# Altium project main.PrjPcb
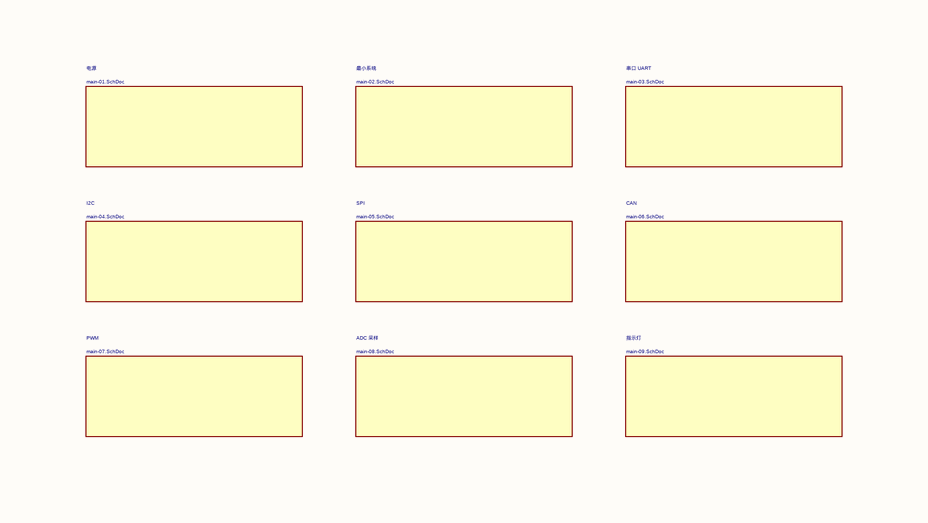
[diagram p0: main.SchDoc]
10 sheets, 84 parts. Net scope: global (net labels, ports and power ports of the same name join across sheets).
Board file: main.PcbDoc
Sheets:
  main.SchDoc
    电源 = main-01.SchDoc
    最小系统 = main-02.SchDoc
    串口 UART = main-03.SchDoc
    I2C = main-04.SchDoc
    SPI = main-05.SchDoc
    CAN = main-06.SchDoc
    PWM = main-07.SchDoc
    ADC 采样 = main-08.SchDoc
    指示灯 = main-09.SchDoc

## Sheet main.SchDoc
size 172 x 96 mm

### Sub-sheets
ADC 采样 = main-08.SchDoc: no entries
CAN = main-06.SchDoc: no entries
I2C = main-04.SchDoc: no entries
PWM = main-07.SchDoc: no entries
SPI = main-05.SchDoc: no entries
串口 UART = main-03.SchDoc: no entries
指示灯 = main-09.SchDoc: no entries
最小系统 = main-02.SchDoc: no entries
电源 = main-01.SchDoc: no entries

## Sheet main-01.SchDoc
size 171 x 140 mm
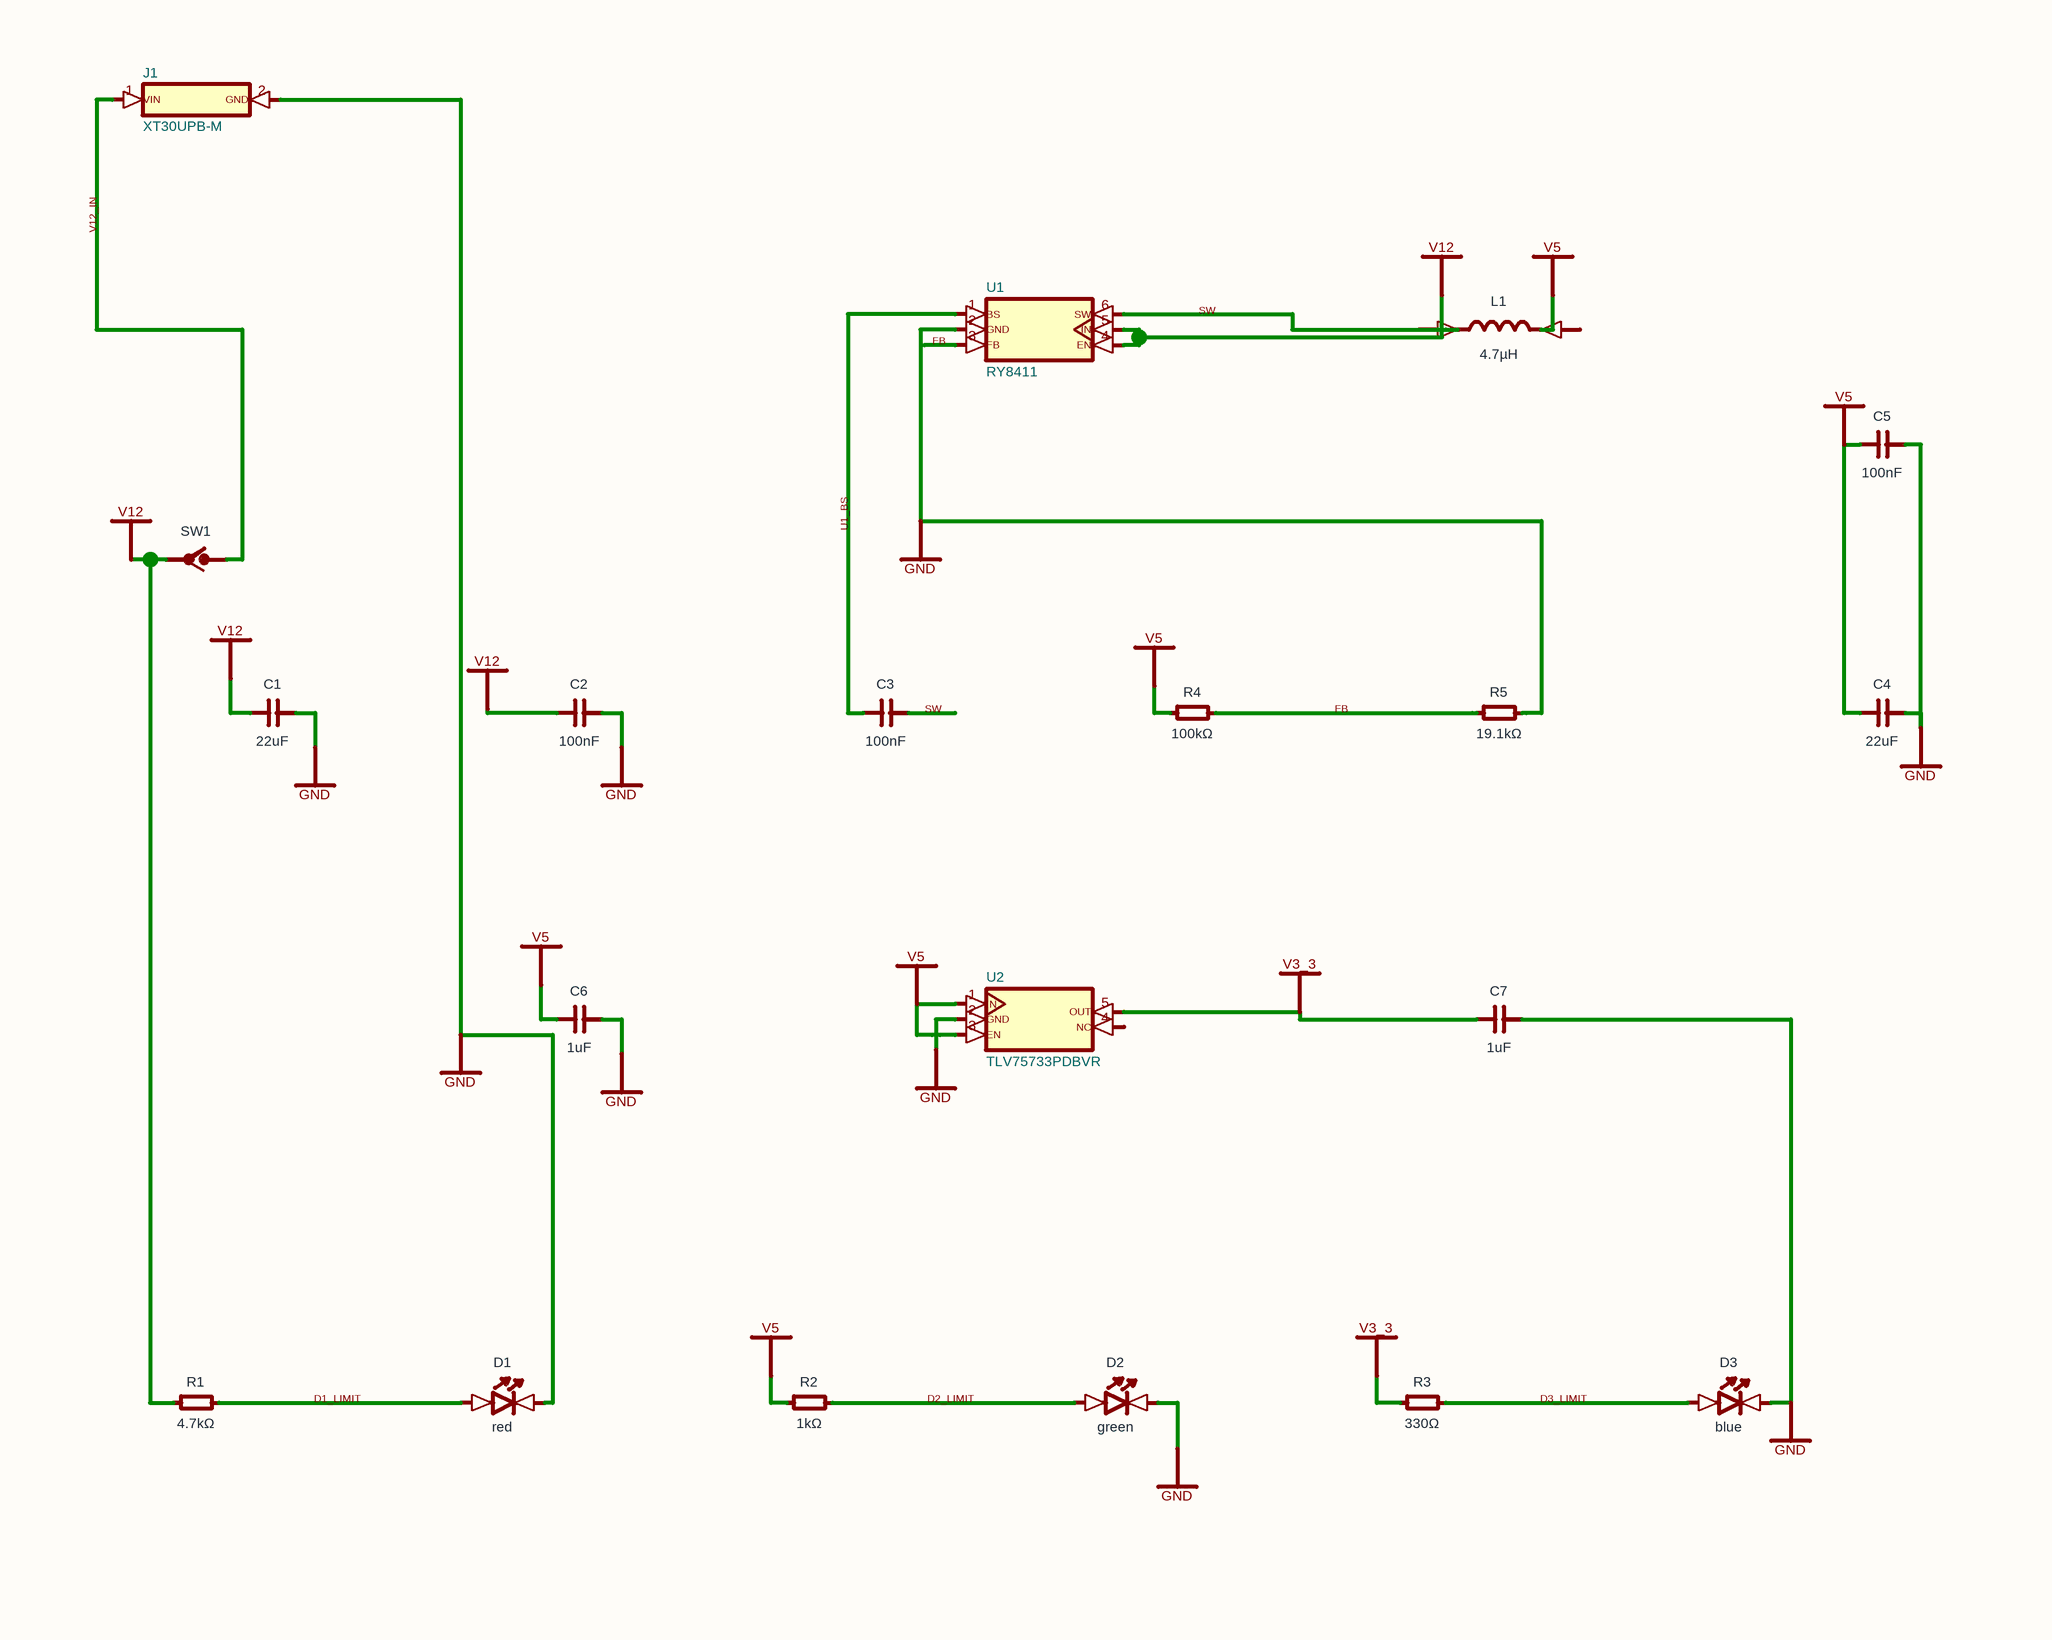
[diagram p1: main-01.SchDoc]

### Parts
C1  22uF
C2  100nF
C3  100nF
C4  22uF
C5  100nF
C6  1uF
C7  1uF
D1  red
D2  green
D3  blue
J1  (no value)
L1  4.7µH
R1  4.7kΩ
R2  1kΩ
R3  330Ω
R4  100kΩ
R5  19.1kΩ
SW1  (no value)
U1  (no value)
U2  (no value)

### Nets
GND: C1.2(neg) C2.2(neg) C4.2(neg) C5.2(neg) C6.2(neg) C7.1(pos) C7.2(neg) D1.2(cathode) D2.1(cathode) D3.1(cathode) J1.2(GND) R3.1(anode) R5.2(cathode) U1.2(GND) U2.2(GND) U2.5(OUT)  [also labelled V3_3]
V5: C4.1(pos) C5.1(pos) C6.1(pos) R2.1(anode) R4.1(anode) U2.1(IN) U2.3(EN)
V12: C1.1(pos) C2.1(pos) R1.1(anode) SW1.1(T1) U1.4(EN) U1.5(IN)
NetC3_1: C3.1(pos) U1.1(BS)
NetD1_1: D1.1(anode) R1.2(cathode)
NetD2_2: D2.2(anode) R2.2(cathode)
NetD3_2: D3.2(anode) R3.2(cathode)
NetJ1_1: J1.1(VIN) SW1.2(COM)
NetL1_1: L1.1(anode) U1.6(SW)
NetR4_2: R4.2(cathode) R5.1(anode)

Not connected (* = marked no-connect by the designer): C3 2(neg); L1 2(cathode); U1 3(FB); U2 4(NC)

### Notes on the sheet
- (near J1) V12_IN
- (near U1) FB
- (near U1) SW
- U1_BS
- (near C3) SW
- FB
- D1_LIMIT
- D2_LIMIT
- D3_LIMIT

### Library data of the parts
C1-C7 = capacitor_right
D1-D3 = led_right
J1 = J1
L1 = inductor_right
R1-R5 = boxresistor_right
SW1 = spst_switch_right
U1 = U1
U2 = U2

## Sheet main-02.SchDoc
size 167 x 125 mm
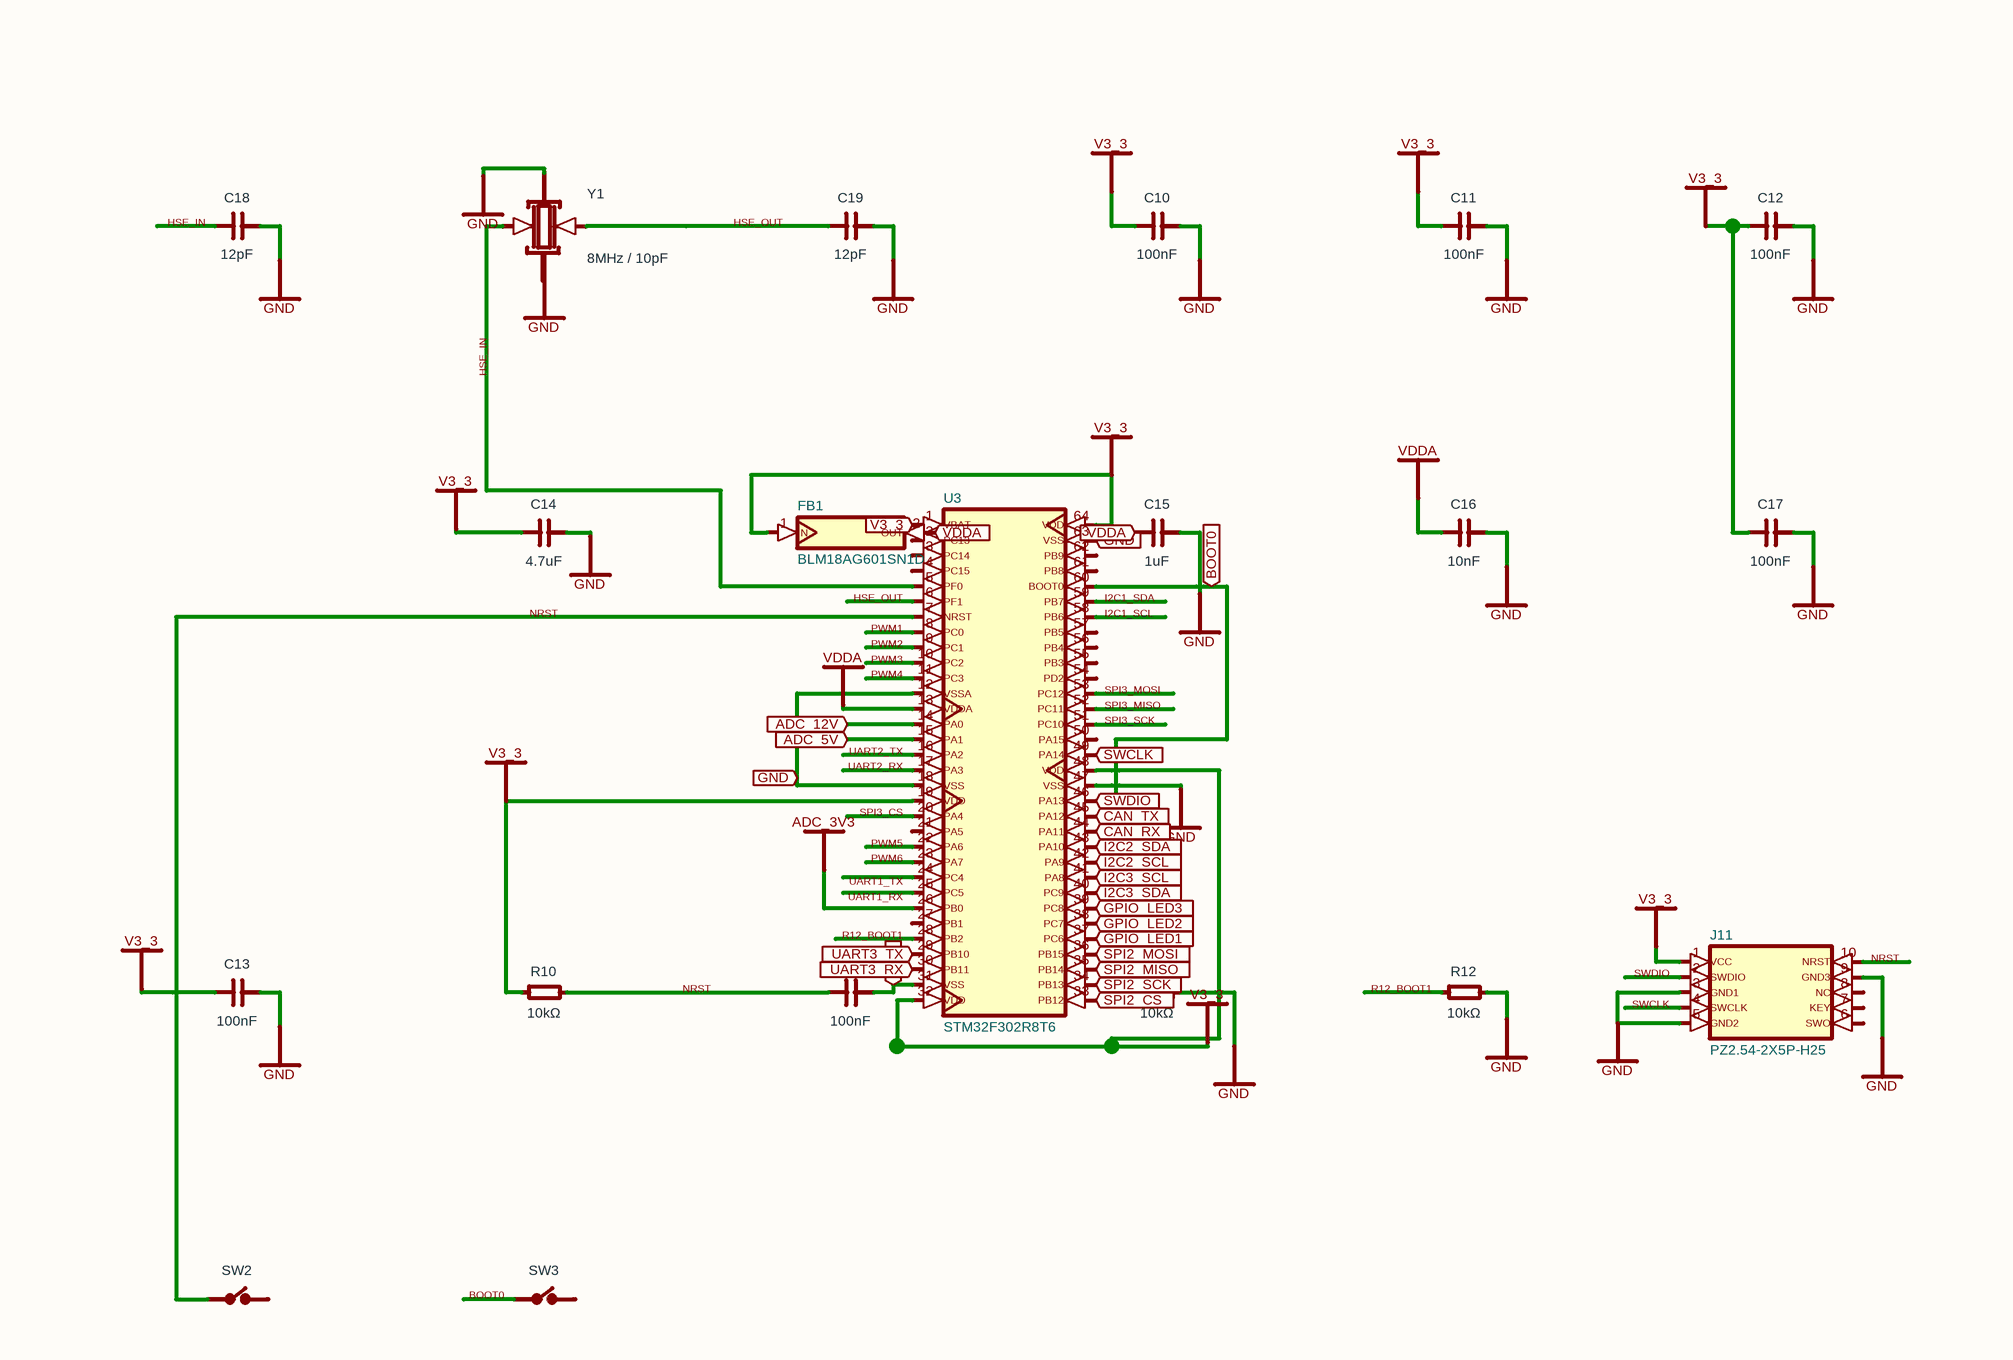
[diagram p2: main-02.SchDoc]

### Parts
C10  100nF
C11  100nF
C12  100nF
C13  100nF
C14  4.7uF
C15  1uF
C16  10nF
C17  100nF
C18  12pF
C19  12pF
C20  100nF
FB1  (no value)
J11  (no value)
R10  10kΩ
R11  10kΩ
R12  10kΩ
SW2  (no value)
SW3  (no value)
U3  (no value)
Y1  8MHz / 10pF

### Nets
ADC_3V3: U3.26(PB0)
ADC_5V: U3.15(PA1)
ADC_12V: U3.14(PA0)
GND: C10.1(pos) C10.2(neg) C11.1(pos) C11.2(neg) C12.1(pos) C12.2(neg) C13.1(pos) C13.2(neg) C14.1(pos) C14.2(neg) C15.2(neg) C16.2(neg) C17.1(pos) C17.2(neg) C18.2(neg) C19.2(neg) C20.2(neg) FB1.1(IN) J11.1(VCC) J11.3(GND1) J11.5(GND2) J11.9(GND3) R10.1(anode) R11.2(cathode) R12.2(cathode) SW2.1(A1) U3.1(VBAT) U3.7(NRST) U3.12(VSSA) U3.18(VSS) U3.19(VDD) U3.31(VSS) U3.32(VDD) U3.47(VSS) U3.48(VDD) U3.63(VSS) U3.64(VDD) Y1.2(gnd2) Y1.4(gnd1)  [also labelled V3_3]
VDDA: C15.1(pos) C16.1(pos) FB1.2(OUT) U3.13(VDDA)
BOOT0: R11.1(anode) U3.60(BOOT0)
CAN_RX: U3.44(PA11)
CAN_TX: U3.45(PA12)
GPIO_LED1: U3.37(PC6)
GPIO_LED2: U3.38(PC7)
GPIO_LED3: U3.39(PC8)
I2C2_SCL: U3.42(PA9)
I2C2_SDA: U3.43(PA10)
I2C3_SCL: U3.41(PA8)
I2C3_SDA: U3.40(PC9)
SPI2_CS: U3.33(PB12)
SPI2_MISO: U3.35(PB14)
SPI2_MOSI: U3.36(PB15)
SPI2_SCK: U3.34(PB13)
SWCLK: U3.49(PA14)
SWDIO: U3.46(PA13)
UART3_RX: U3.30(PB11)
UART3_TX: U3.29(PB10)
NetC19_1: C19.1(pos) Y1.3(X2)
NetC20_1: C20.1(pos) R10.2(cathode)
NetU3_5: U3.5(PF0) Y1.1(X1)

Not connected (* = marked no-connect by the designer): C18 1(pos); J11 2(SWDIO) 4(SWCLK) 6(SWO) 7(KEY) 8(NC) 10(NRST); R12 1(anode); SW2 2(A2); SW3 1(A1) 2(A2); U3 2(PC13) 3(PC14) 4(PC15) 6(PF1) 8(PC0) 9(PC1) 10(PC2) 11(PC3) 16(PA2) 17(PA3) 20(PA4) 21(PA5) 22(PA6) 23(PA7) 24(PC4) 25(PC5) 27(PB1) 28(PB2) 50(PA15) 51(PC10) 52(PC11) 53(PC12) 54(PD2) 55(PB3) 56(PB4) 57(PB5) 58(PB6) 59(PB7) 61(PB8) 62(PB9)

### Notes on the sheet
- (near C18) HSE_IN
- (near C19) HSE_OUT
- (near Y1) HSE_IN
- (near C14) NRST
- HSE_OUT
- (near U3) PWM1
- (near U3) I2C1_SCL
- I2C1_SDA
- (near U3) PWM2
- (near U3) PWM3
- (near U3) PWM4
- (near U3) UART2_TX
- (near U3) UART2_RX
- (near U3) SPI3_CS
- (near U3) SPI3_SCK
- (near U3) SPI3_MISO
- (near U3) SPI3_MOSI
- NRST
- R12_BOOT1
- (near U3) PWM5
- (near U3) PWM6
- (near U3) UART1_TX
- (near U3) UART1_RX
- (near R12) R12_BOOT1
- (near J11) SWDIO
- (near J11) SWCLK
- (near J11) NRST
- (near SW3) BOOT0

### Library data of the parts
C10-C20 = capacitor_right
FB1 = FB1
J11 = J11
R10-R12 = boxresistor_right
SW2 SW3 = spst_switch_right
U3 = U3
Y1 = crystal_4pin_right

## Sheet main-03.SchDoc
size 101 x 114 mm
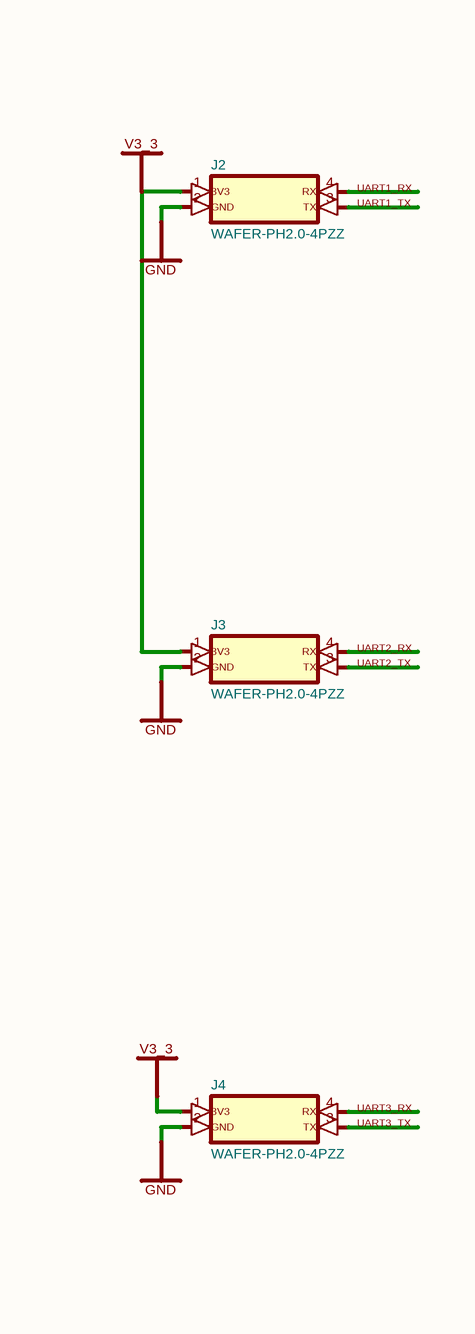
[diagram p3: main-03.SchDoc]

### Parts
J2  (no value)
J3  (no value)
J4  (no value)

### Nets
GND: J2.1(3V3) J2.2(GND) J3.1(3V3) J3.2(GND) J4.1(3V3) J4.2(GND)  [also labelled V3_3]

Not connected (* = marked no-connect by the designer): J2 3(TX) 4(RX); J3 3(TX) 4(RX); J4 3(TX) 4(RX)

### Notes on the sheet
- (near J2) UART1_TX
- (near J2) UART1_RX
- (near J3) UART2_TX
- (near J3) UART2_RX
- (near J4) UART3_TX
- (near J4) UART3_RX

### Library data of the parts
J2 = J2
J3 = J3
J4 = J4

## Sheet main-04.SchDoc
size 158 x 97 mm
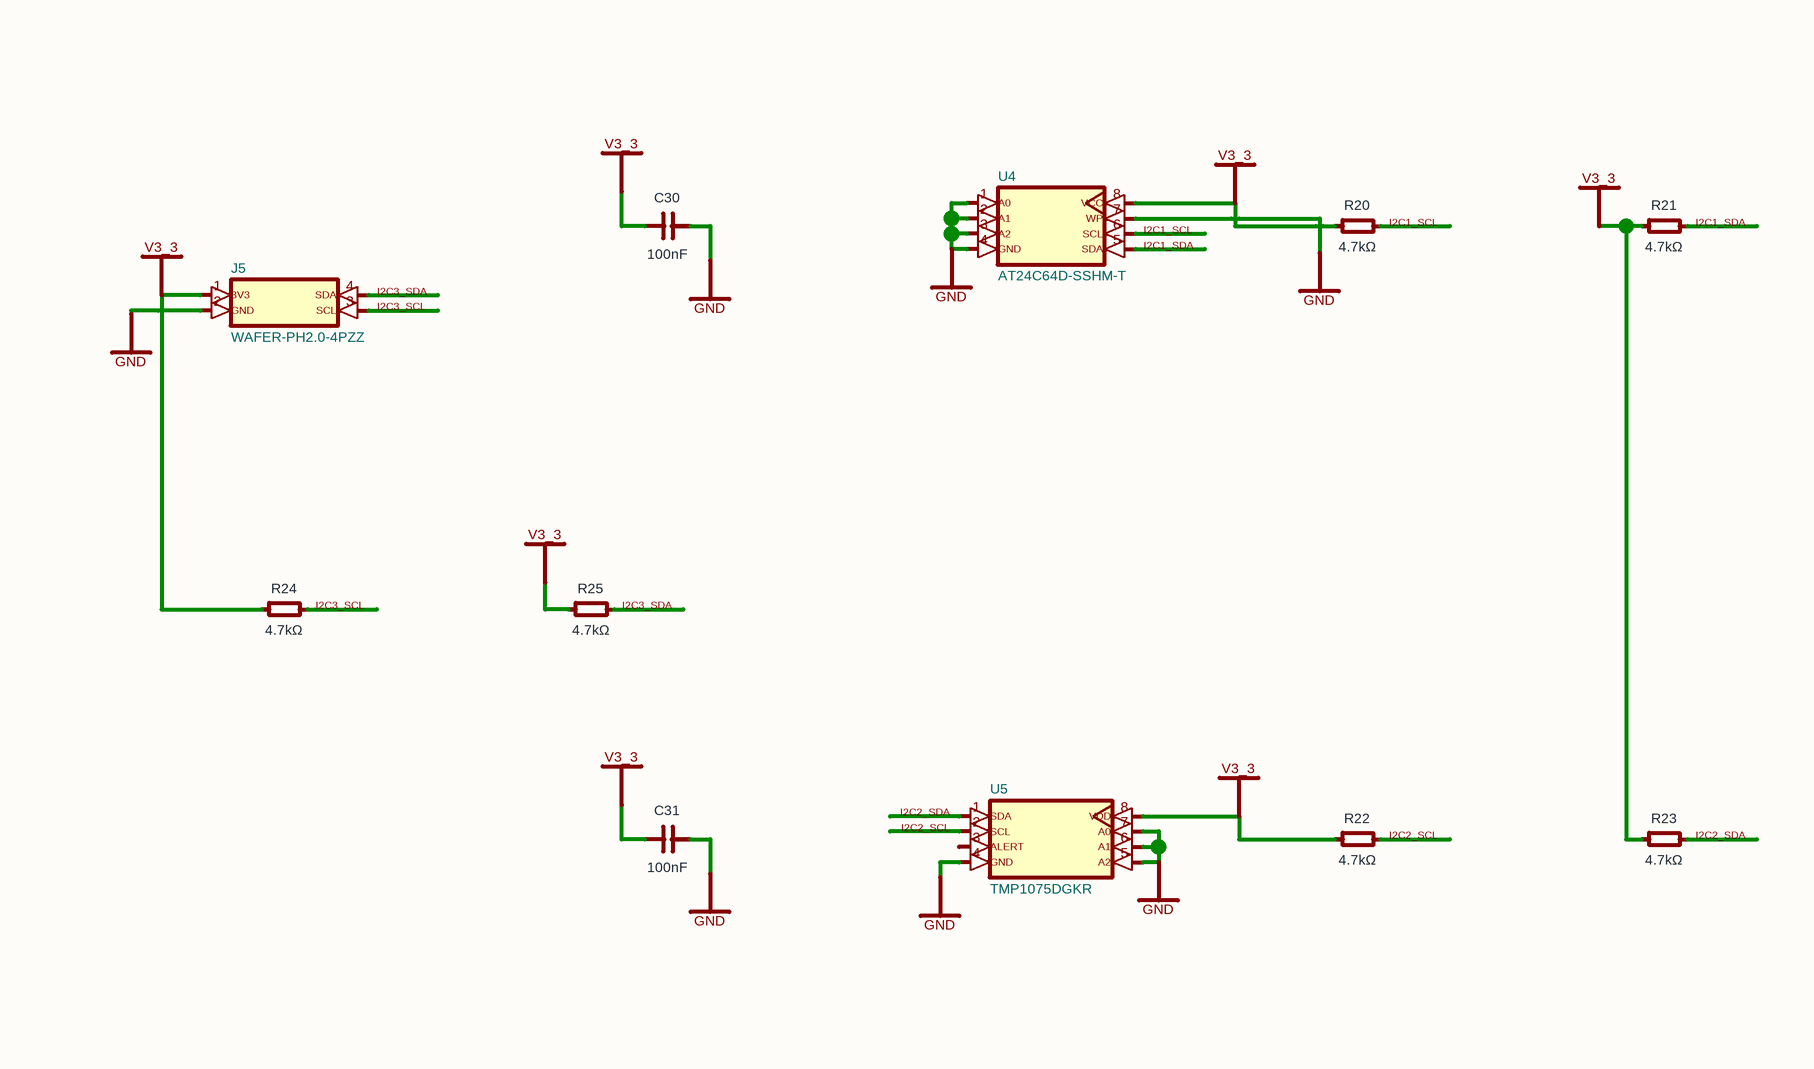
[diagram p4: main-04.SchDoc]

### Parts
C30  100nF
C31  100nF
J5  (no value)
R20  4.7kΩ
R21  4.7kΩ
R22  4.7kΩ
R23  4.7kΩ
R24  4.7kΩ
R25  4.7kΩ
U4  (no value)
U5  (no value)

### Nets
GND: C30.1(pos) C30.2(neg) C31.1(pos) C31.2(neg) J5.1(3V3) J5.2(GND) R20.1(anode) R21.1(anode) R22.1(anode) R23.1(anode) R24.1(anode) R25.1(anode) U4.1(A0) U4.2(A1) U4.3(A2) U4.4(GND) U4.7(WP) U4.8(VCC) U5.4(GND) U5.5(A2) U5.6(A1) U5.7(A0) U5.8(VDD)  [also labelled V3_3]

Not connected (* = marked no-connect by the designer): J5 3(SCL) 4(SDA); R20 2(cathode); R21 2(cathode); R22 2(cathode); R23 2(cathode); R24 2(cathode); R25 2(cathode); U4 5(SDA) 6(SCL); U5 1(SDA) 2(SCL) 3(ALERT)

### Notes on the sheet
- (near J5) I2C3_SCL
- (near J5) I2C3_SDA
- (near U4) I2C1_SDA
- (near U4) I2C1_SCL
- (near R20) I2C1_SCL
- (near R21) I2C1_SDA
- (near R24) I2C3_SCL
- (near R25) I2C3_SDA
- (near U5) I2C2_SDA
- (near U5) I2C2_SCL
- (near R22) I2C2_SCL
- (near R23) I2C2_SDA

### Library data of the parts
C30 C31 = capacitor_right
J5 = J5
R20-R25 = boxresistor_right
U4 = U4
U5 = U5

## Sheet main-05.SchDoc
size 135 x 133 mm
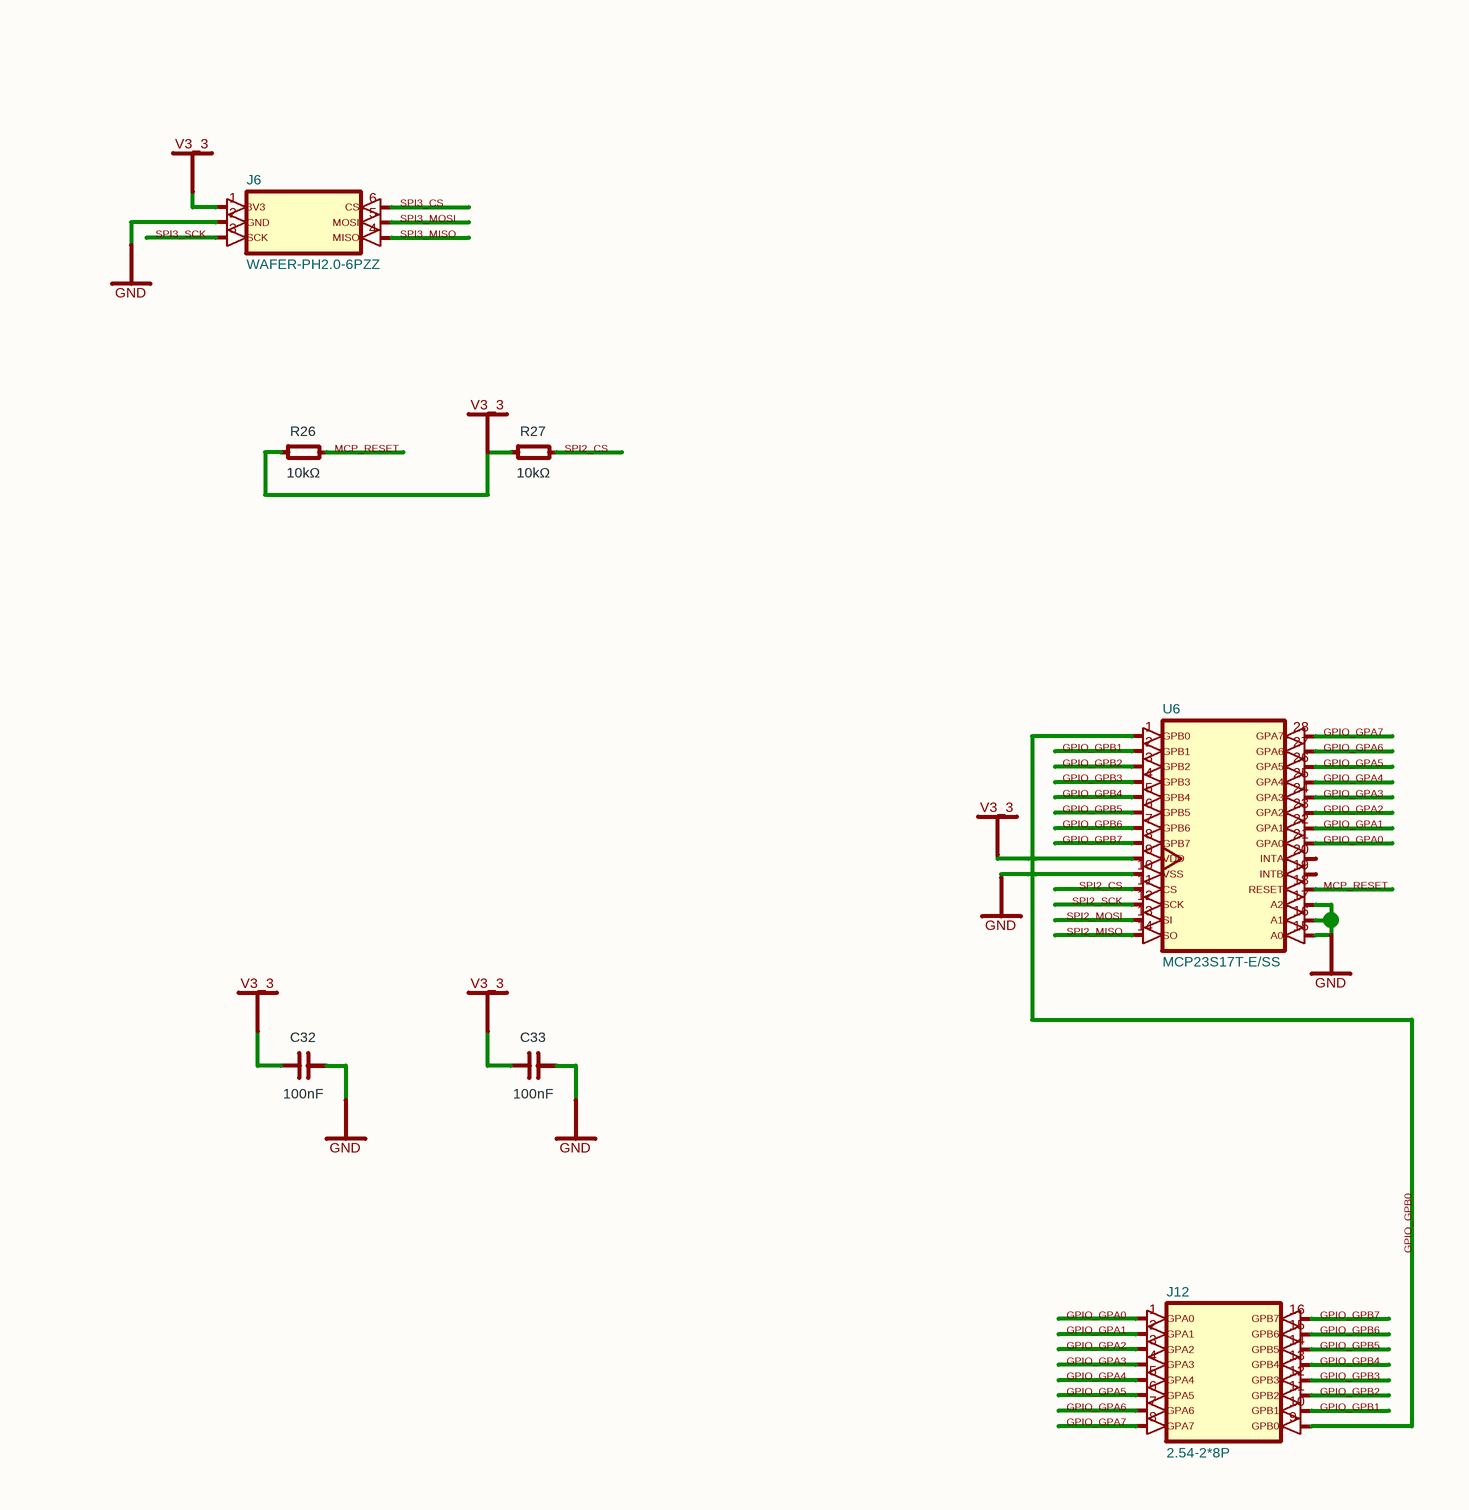
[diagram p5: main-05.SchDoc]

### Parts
C32  100nF
C33  100nF
J6  (no value)
J12  (no value)
R26  10kΩ
R27  10kΩ
U6  (no value)

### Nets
GND: C32.1(pos) C32.2(neg) C33.1(pos) C33.2(neg) J6.1(3V3) J6.2(GND) R26.1(anode) R27.1(anode) U6.9(VDD) U6.10(VSS) U6.15(A0) U6.16(A1) U6.17(A2)  [also labelled V3_3]
NetJ12_9: J12.9(GPB0) U6.1(GPB0)

Not connected (* = marked no-connect by the designer): J6 3(SCK) 4(MISO) 5(MOSI) 6(CS); J12 1(GPA0) 2(GPA1) 3(GPA2) 4(GPA3) 5(GPA4) 6(GPA5) 7(GPA6) 8(GPA7) 10(GPB1) 11(GPB2) 12(GPB3) 13(GPB4) 14(GPB5) 15(GPB6) 16(GPB7); R26 2(cathode); R27 2(cathode); U6 2(GPB1) 3(GPB2) 4(GPB3) 5(GPB4) 6(GPB5) 7(GPB6) 8(GPB7) 11(CS) 12(SCK) 13(SI) 14(SO) 18(RESET) 19(INTB) 20(INTA) 21(GPA0) 22(GPA1) 23(GPA2) 24(GPA3) 25(GPA4) 26(GPA5) 27(GPA6) 28(GPA7)

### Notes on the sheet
- (near J6) SPI3_SCK
- (near J6) SPI3_MISO
- (near J6) SPI3_MOSI
- (near J6) SPI3_CS
- (near R26) MCP_RESET
- (near R27) SPI2_CS
- (near U6) GPIO_GPB1
- (near U6) GPIO_GPA6
- (near U6) GPIO_GPA7
- (near U6) GPIO_GPB2
- (near U6) GPIO_GPB3
- (near U6) GPIO_GPB4
- (near U6) GPIO_GPB5
- (near U6) GPIO_GPB6
- (near U6) GPIO_GPB7
- (near U6) SPI2_CS
- (near U6) SPI2_SCK
- (near U6) SPI2_MOSI
- (near U6) SPI2_MISO
- (near U6) GPIO_GPA0
- (near U6) GPIO_GPA1
- (near U6) GPIO_GPA2
- (near U6) GPIO_GPA3
- (near U6) GPIO_GPA4
- (near U6) GPIO_GPA5
- (near U6) MCP_RESET
- (near J12) GPIO_GPA0
- (near J12) GPIO_GPB7
- (near J12) GPIO_GPB0
- (near J12) GPIO_GPA1
- (near J12) GPIO_GPA2
- (near J12) GPIO_GPA3
- (near J12) GPIO_GPA4
- (near J12) GPIO_GPA5
- (near J12) GPIO_GPA6
- (near J12) GPIO_GPA7
- (near J12) GPIO_GPB1
- (near J12) GPIO_GPB2
- (near J12) GPIO_GPB3
- (near J12) GPIO_GPB4
- (near J12) GPIO_GPB5
- (near J12) GPIO_GPB6

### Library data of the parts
C32 C33 = capacitor_right
J6 = J6
J12 = J12
R26 R27 = boxresistor_right
U6 = U6

## Sheet main-06.SchDoc
size 156 x 94 mm
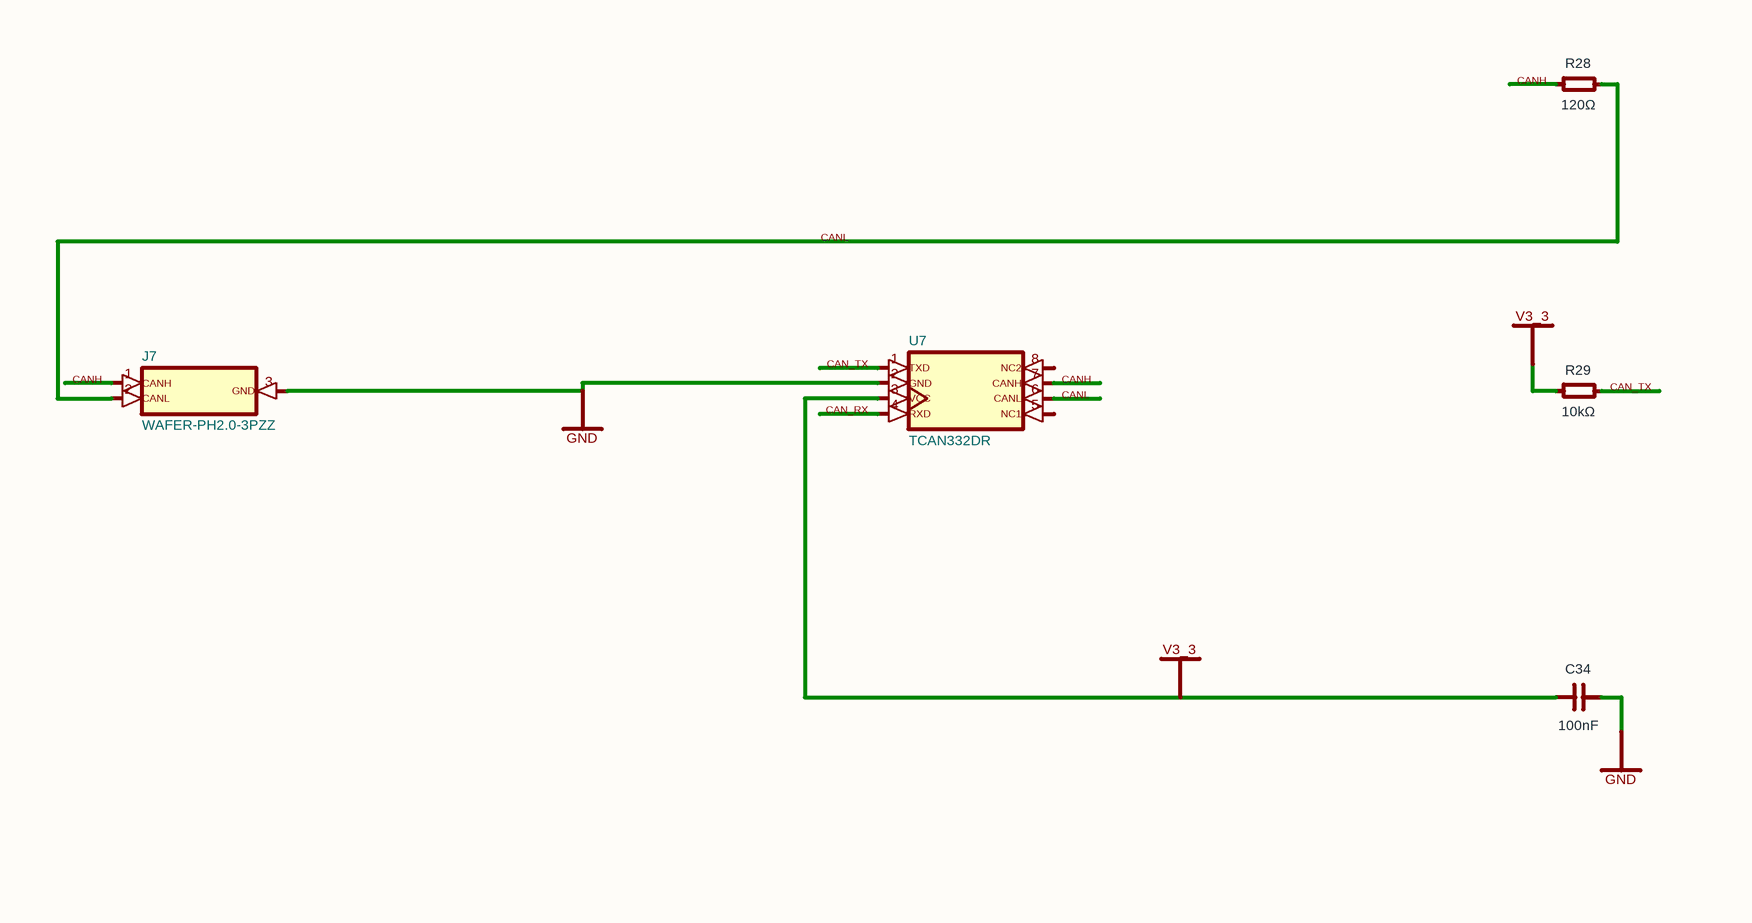
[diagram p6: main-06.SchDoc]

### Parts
C34  100nF
J7  (no value)
R28  120Ω
R29  10kΩ
U7  (no value)

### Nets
GND: C34.1(pos) C34.2(neg) J7.3(GND) R29.1(anode) U7.2(GND) U7.3(VCC)  [also labelled V3_3]
NetJ7_2: J7.2(CANL) R28.2(cathode)

Not connected (* = marked no-connect by the designer): J7 1(CANH); R28 1(anode); R29 2(cathode); U7 1(TXD) 4(RXD) 5(NC1) 6(CANL) 7(CANH) 8(NC2)

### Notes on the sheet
- (near U7) CANL
- (near R28) CANH
- (near J7) CANH
- (near U7) CAN_TX
- (near U7) CAN_RX
- (near U7) CANH
- (near R29) CAN_TX

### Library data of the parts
C34 = capacitor_right
J7 = J7
R28 R29 = boxresistor_right
U7 = U7

## Sheet main-07.SchDoc
size 101 x 124 mm
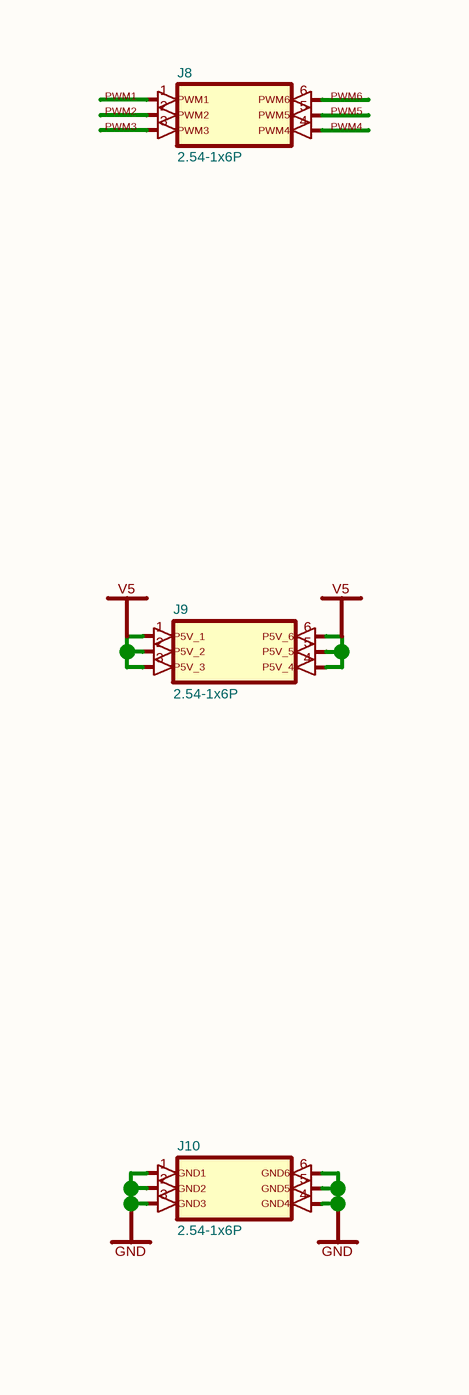
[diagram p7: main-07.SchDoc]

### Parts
J8  (no value)
J9  (no value)
J10  (no value)

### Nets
GND: J10.1(GND1) J10.2(GND2) J10.3(GND3) J10.4(GND4) J10.5(GND5) J10.6(GND6)
V5: J9.1(P5V_1) J9.2(P5V_2) J9.3(P5V_3) J9.4(P5V_4) J9.5(P5V_5) J9.6(P5V_6)

Not connected (* = marked no-connect by the designer): J8 1(PWM1) 2(PWM2) 3(PWM3) 4(PWM4) 5(PWM5) 6(PWM6)

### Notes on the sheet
- (near J8) PWM1
- (near J8) PWM2
- (near J8) PWM3
- (near J8) PWM4
- (near J8) PWM5
- (near J8) PWM6

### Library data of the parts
J8 = J8
J9 = J9
J10 = J10

## Sheet main-08.SchDoc
size 141 x 96 mm
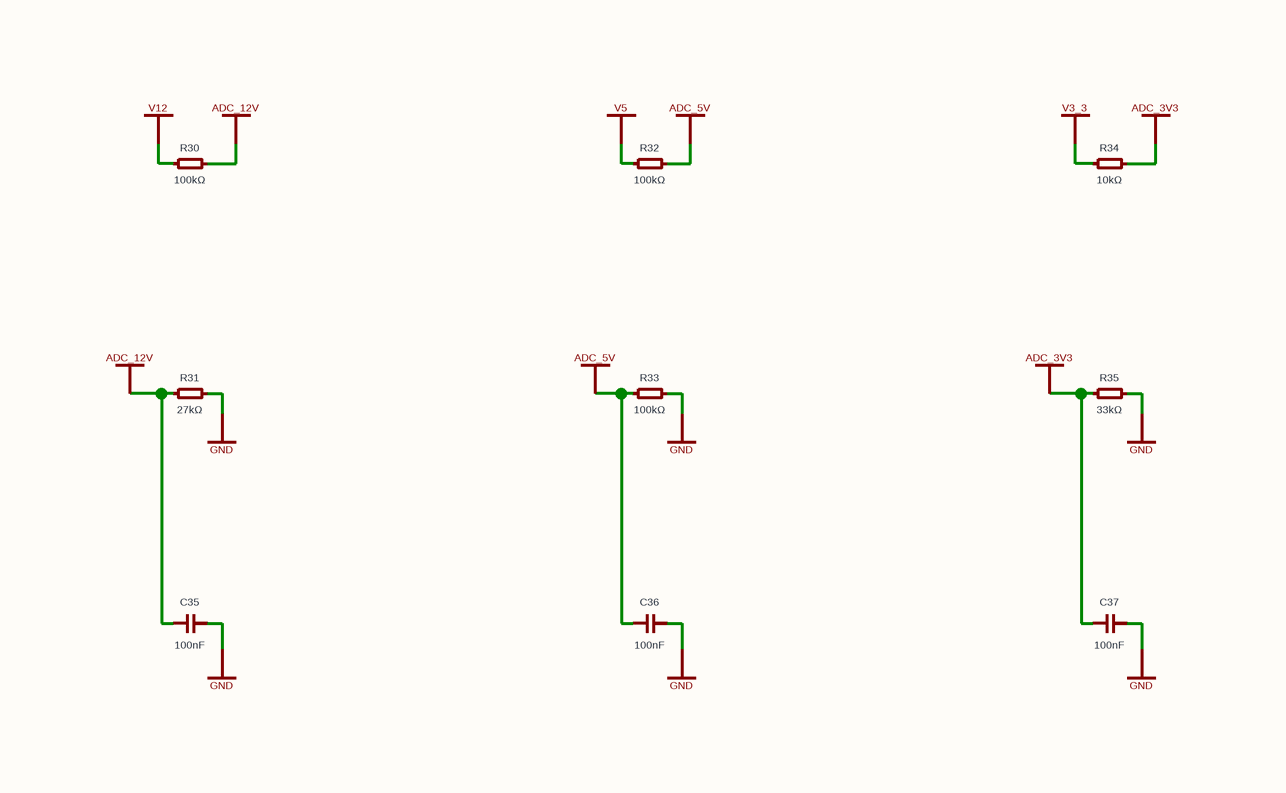
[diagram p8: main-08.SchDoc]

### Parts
C35  100nF
C36  100nF
C37  100nF
R30  100kΩ
R31  27kΩ
R32  100kΩ
R33  100kΩ
R34  10kΩ
R35  33kΩ

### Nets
ADC_3V3: C37.1(pos) R34.2(cathode) R35.1(anode)
ADC_5V: C36.1(pos) R32.2(cathode) R33.1(anode)
ADC_12V: C35.1(pos) R30.2(cathode) R31.1(anode)
GND: C35.2(neg) C36.2(neg) C37.2(neg) R31.2(cathode) R33.2(cathode) R34.1(anode) R35.2(cathode)  [also labelled V3_3]
V5: R32.1(anode)
V12: R30.1(anode)

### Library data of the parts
C35-C37 = capacitor_right
R30-R35 = boxresistor_right

## Sheet main-09.SchDoc
size 101 x 101 mm
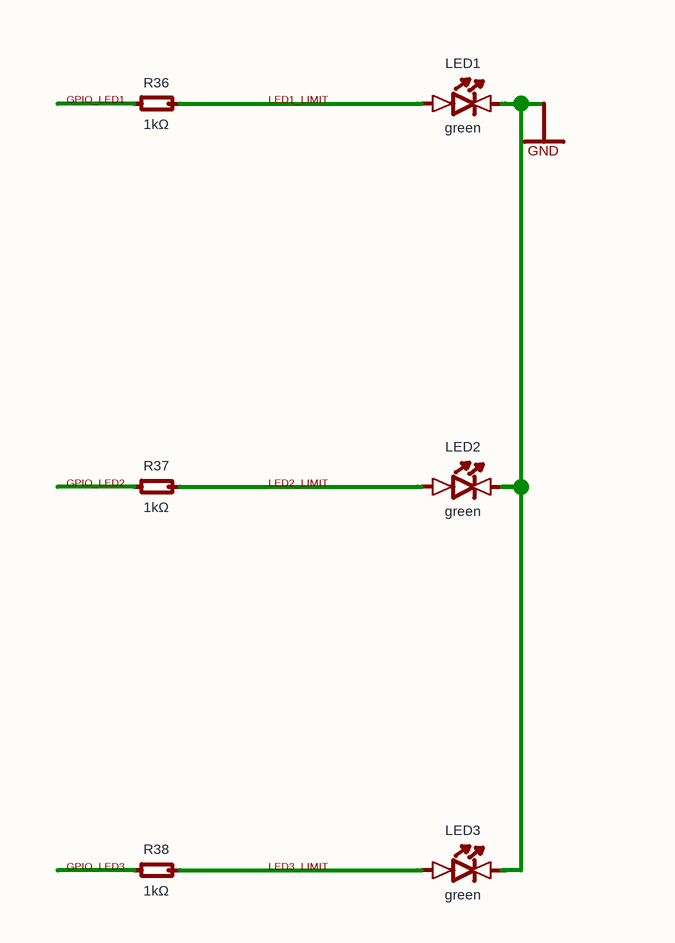
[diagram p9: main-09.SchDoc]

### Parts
LED1  green
LED2  green
LED3  green
R36  1kΩ
R37  1kΩ
R38  1kΩ

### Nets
GND: LED1.1(cathode) LED2.1(cathode) LED3.1(cathode)
NetLED1_2: LED1.2(anode) R36.2(cathode)
NetLED2_2: LED2.2(anode) R37.2(cathode)
NetLED3_2: LED3.2(anode) R38.2(cathode)

Not connected (* = marked no-connect by the designer): R36 1(anode); R37 1(anode); R38 1(anode)

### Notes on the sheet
- (near R36) GPIO_LED1
- LED1_LIMIT
- (near R37) GPIO_LED2
- LED2_LIMIT
- (near R38) GPIO_LED3
- LED3_LIMIT

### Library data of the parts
LED1-LED3 = led_right
R36-R38 = boxresistor_right

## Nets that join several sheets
ADC_3V3: main-02 (U3.26), main-08 (C37.1 R34.2 R35.1)
ADC_5V: main-02 (U3.15), main-08 (C36.1 R32.2 R33.1)
ADC_12V: main-02 (U3.14), main-08 (C35.1 R30.2 R31.1)
GND: main-01 (16 pins), main-02 (39 pins), main-03 (6 pins), main-04 (23 pins), main-05 (13 pins), main-06 (6 pins), main-07 (6 pins), main-08 (7 pins), main-09 (LED1.1 LED2.1 LED3.1)
V5: main-01 (7 pins), main-07 (6 pins), main-08 (R32.1)
V12: main-01 (6 pins), main-08 (R30.1)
